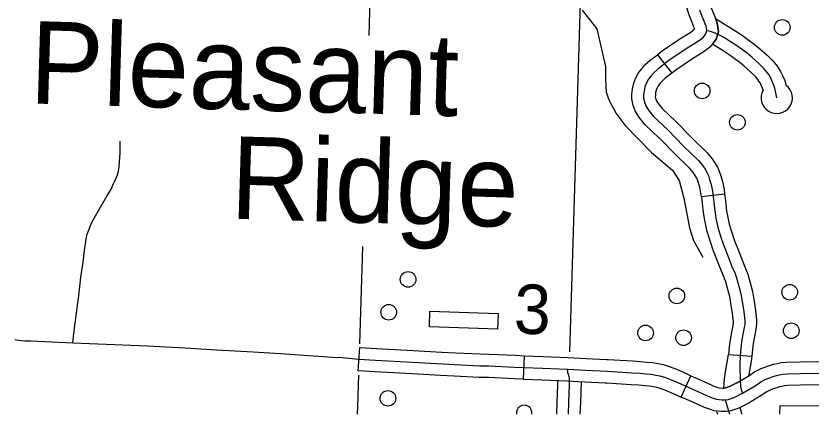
# Model space of a CAD drawing. Extents: x 653372 to 905732, y 627442 to 787275.
# Drawn here: x 695550 to 700643, y 728634 to 731183 of the extents above; entities that cross this region are included whole.
import ezdxf

# ---------------------------------------------------------------- set-up
doc = ezdxf.new("R2010")
doc.units = 0
for name, color, linetype in [('25', 7, 'Continuous'), ('31', 7, 'Continuous'), ('33', 7, 'Continuous'), ('35', 7, 'Continuous'), ('45', 7, 'Continuous'), ('5', 7, 'Continuous'), ('56', 7, 'Continuous'), ('6', 7, 'Continuous')]:
    doc.layers.add(name, color=color, linetype=linetype)

msp = doc.modelspace()

# ---------------------------------------------------------------- linework, layer by layer
at = {"layer": '31'}
for p, q in [((699658.2, 730935), (699750.2, 730816.5)), ((699773.6, 730509.8), (699773.6, 730509.8)), ((700089, 730042.6), (699940.2, 730024.1)), ((697741.2, 728911), (697751.9, 729060.6)), ((698804.4, 729007.3), (698797.9, 728857.4)), ((700113.6, 729014.9), (700263.3, 729004.1)), ((698270, 728881.2), (698270, 728881.2)), ((699810.7, 728742.9), (699872.9, 728879.4)), ((699872.9, 728879.4), (699872.9, 728879.4))]:
    msp.add_line(p, q, dxfattribs=at)
for points in [[(699844.1, 731243.5), (699846.2, 731233.1), (699856.9, 731197.1), (699874.1, 731153.1), (699889.1, 731116.2), (699895, 731098.1), (699895.1, 731097.8), (699890.1, 731092.1), (699872, 731077.9), (699801.9, 731034.8), (699688.2, 730958.4), (699658.2, 730935)], [(699991, 731273.9), (699991.9, 731269.6), (699998.9, 731245.7), (700013.4, 731208.8), (700030.1, 731167.8), (700040.2, 731136.7), (700045.8, 731109.7), (700049.8, 731081.3), (700034.5, 731035), (700015.7, 731007.8), (699993.6, 730982.6), (699957.8, 730954.6), (699883.1, 730908.6), (699776.2, 730836.7), (699750.2, 730816.5)], [(699927.9, 731221.4), (699943.7, 731181), (699959.6, 731142), (699967.6, 731117.4), (699971.9, 731096.8), (699973.1, 731088.2), (699966.6, 731068.8), (699956.5, 731054), (699941.8, 731037.4), (699914.9, 731016.2), (699842.5, 730971.7), (699732.2, 730897.5), (699660.9, 730842.2)], [(700010.9, 731002.3), (700034.5, 731035), (700049.8, 731081.3), (700040.2, 731136.7), (700030.2, 731167.5), (700160.8, 731085.1), (700209.3, 731053.3), (700247, 731026.8), (700279, 731003.2), (700313, 730975.2), (700360.8, 730931.8), (700395, 730897), (700418.5, 730870.8), (700433.7, 730849.5), (700447.3, 730827.4), (700460.2, 730801.9), (700473.6, 730769.8), (700482.6, 730738.4)], [(700422.7, 730658.3), (700416.9, 730691.2), (700409.4, 730721.4), (700402.7, 730744.9), (700392, 730770.6), (700381.8, 730790.8), (700371.2, 730808), (700359.8, 730823.8), (700340.3, 730845.7), (700308.8, 730877.7), (700263.8, 730918.5), (700232.9, 730944.1), (700203.2, 730965.9), (700167.2, 730991.3), (700120.2, 731022), (700088.8, 731041.9), (700056.2, 731059.4), (700027.3, 731073.1), (700003.9, 731081.9), (699989.9, 731085.3), (699973.1, 731088.2)], [(700335.5, 730707.2), (700331.8, 730720.1), (700323.8, 730739.2), (700316.3, 730754.1), (700308.7, 730766.4), (700301.2, 730776.9), (700285.6, 730794.3), (700256.8, 730823.6), (700214.7, 730861.8), (700186.8, 730884.9), (700159.4, 730905), (700125, 730929.2), (700079.6, 730958.9), (700010.9, 731002.3)], [(699670.5, 730400.9), (699578.4, 730488), (699539.7, 730536), (699515.5, 730574.8), (699502.7, 730609.8), (699494.5, 730651.8), (699495.4, 730682.3), (699498.3, 730715.5), (699507, 730752.8), (699521, 730786.8), (699537.6, 730818.9), (699558.1, 730845.1), (699578.6, 730869.3), (699612.9, 730899.9), (699658.2, 730935)], [(699660.9, 730842.2), (699632.4, 730816.8), (699616.2, 730797.8), (699601.1, 730778.3), (699589.2, 730755.2), (699578.7, 730729.8), (699572.5, 730703.6), (699570.3, 730677.9), (699569.7, 730657.9), (699575.2, 730630), (699583.3, 730607.9), (699600.9, 730579.6), (699633.6, 730539), (699724.5, 730453), (699826.1, 730350.2), (699920.6, 730256.7), (699948.3, 730222.8), (699963.3, 730201.4), (699976.7, 730178.6), (699985, 730161.3), (699993, 730136.7), (700002.2, 730104.3), (700011.2, 730061.1), (700019.8, 729991.6), (700023.9, 729949.1), (700027.5, 729922.7), (700032.8, 729888.4), (700046.1, 729830.1), (700063.4, 729773.6), (700082.1, 729717), (700102.4, 729663.8), (700135.5, 729579.5), (700153.2, 729538.6), (700165.4, 729506), (700180.4, 729453.5), (700193, 729403.8), (700203.3, 729341.7), (700211.5, 729289.3), (700216.1, 729250.7), (700218.4, 729229.7), (700218.5, 729214.6), (700217.2, 729204.4), (700214.8, 729188.9), (700208.4, 729155.5), (700197.4, 729096.8), (700191.8, 729055.6), (700188.4, 729009.4), (700185.5, 728944.2), (700187.5, 728847.2), (700190.8, 728812.6), (700195.5, 728790), (700203.1, 728767.9)], [(699750.2, 730816.5), (699708.9, 730784.5), (699686.2, 730764.3), (699674.4, 730750.4), (699664.5, 730737.7), (699657.3, 730723.7), (699650.3, 730706.7), (699646.8, 730691.8), (699645.2, 730673.5), (699644.9, 730664.1), (699647.6, 730650.2), (699651, 730640.9), (699662.2, 730623.1), (699688.8, 730590.1), (699773.6, 730509.8)], [(699773.6, 730509.8), (699777, 730506.6), (699879.1, 730403.2), (699976.2, 730307.3), (700008.2, 730268), (700026.4, 730242), (700043, 730213.8), (700054.8, 730189.2), (700064.7, 730158.6), (700075.1, 730122.2), (700085.2, 730073.4), (700089, 730042.6)], [(699940.2, 730024.1), (699937.1, 730048.9), (699929.4, 730086.4), (699921.3, 730114.8), (699915.2, 730133.4), (699910.4, 730143.3), (699900.1, 730160.8), (699888.5, 730177.5), (699865.1, 730206.2), (699773, 730297.1), (699672, 730399.4), (699670.5, 730400.9)], [(699940.2, 730024.1), (699945.2, 729983.4), (699949.4, 729940.5), (699953.2, 729911.9), (699959, 729874.3), (699973.6, 729810.7), (699991.9, 729750.8), (700011.5, 729691.8), (700032.5, 729636.7), (700066.1, 729550.9), (700083.6, 729510.5), (700086.9, 729501.7)], [(700089, 730042.6), (700094.3, 729999.8), (700098.4, 729957.7), (700101.7, 729933.5), (700106.5, 729902.6), (700118.6, 729849.4), (700134.9, 729796.3), (700152.8, 729742.2), (700172.4, 729690.8), (700204.8, 729608.1), (700222.8, 729566.6), (700227.4, 729554.3)], [(700227.4, 729554.3), (700236.7, 729529.5), (700252.8, 729473), (700266.5, 729419.2), (700277.3, 729353.6), (700285.8, 729299.6), (700290.6, 729259.3), (700293.4, 729233.8), (700293.5, 729210), (700291.5, 729194), (700288.7, 729176.1), (700282.1, 729141.5), (700271.5, 729084.8), (700266.4, 729047.8), (700263.3, 729004.1)], [(700086.9, 729501.7), (700094.1, 729482.6), (700107.9, 729434), (700119.5, 729388.4), (700129.2, 729329.8), (700137.2, 729279), (700141.6, 729242.1), (700143.4, 729225.5), (700143.5, 729219.2), (700142.9, 729214.8), (700140.9, 729201.7), (700134.7, 729169.4), (700123.3, 729108.8), (700117.1, 729063.3), (700113.6, 729014.9)], [(697751.9, 729060.6), (697858.2, 729053), (698094.6, 729040.1), (698277.4, 729031)], [(698277.4, 729031), (698365.3, 729026.6), (698523.5, 729018.5), (698581.8, 729016.7), (698747.2, 729009.8), (698804.4, 729007.3)], [(698804.4, 729007.3), (698925.5, 729002), (699086.5, 728996.6), (699201.2, 728990.3), (699332.6, 728983.2)], [(700241, 728877), (700166.8, 728833.5), (700120.9, 728809.7), (700093.5, 728800.9), (700083.1, 728799.7), (700087.3, 728859), (700093.5, 728904.4), (700104.9, 728965.1), (700113.6, 729014.9)], [(700263.3, 729004.1), (700258.9, 728971.8), (700252.3, 728937.2), (700241, 728877)], [(697746.6, 728985.8), (697853.5, 728978.2), (698090.6, 728965.2), (698361.5, 728951.7), (698520.5, 728943.5), (698579.1, 728941.8), (698744, 728934.9), (698922.6, 728927.1), (699083.1, 728921.6), (699197.1, 728915.4), (699339.5, 728907.7), (699494.3, 728898.7), (699544.8, 728895.2), (699584.7, 728892.1), (699618.1, 728888.6), (699649.2, 728883.8), (699674.8, 728877.7), (699710.5, 728866.9), (699742.7, 728855.2), (699789.8, 728834.8), (699897.3, 728785.8)], [(699332.6, 728983.2), (699343.7, 728982.6), (699499, 728973.5), (699550.3, 728970), (699591.4, 728966.8), (699627.8, 728963.1), (699663.7, 728957.5), (699694.4, 728950.1), (699734.1, 728938.1), (699770.5, 728924.9), (699820.3, 728903.3), (699872.9, 728879.4)], [(700289.7, 728908.8), (700321.9, 728924.7), (700346.3, 728934.9), (700376.8, 728945.2), (700402.6, 728953.1), (700425, 728957.8), (700450.8, 728963.1), (700484.5, 728966), (700572.4, 728967.7), (700726.6, 728970.7), (700801.3, 728971.9), (700835.6, 728973.3), (700834.5, 728973.2)], [(698270, 728881.2), (698086.7, 728890.3), (697848.7, 728903.3), (697741.2, 728911)], [(699872.9, 728879.4), (699928, 728854.2), (699998.8, 728822.9), (700016.1, 728815), (700039.2, 728806.6), (700053.1, 728802.3), (700074.6, 728799.7), (700086.1, 728799.7), (700093.5, 728800.9), (700120.9, 728809.7), (700166.8, 728833.5), (700243.3, 728878.6), (700282.8, 728905.5), (700289.7, 728908.8)], [(699897.3, 728785.8), (699968, 728754.5), (699987.6, 728745.5), (700015.3, 728735.5), (700037.3, 728728.7), (700070.1, 728724.7), (700092, 728724.8), (700110.8, 728727.6), (700149.9, 728740.3), (700203.1, 728767.9), (700283.5, 728815.2), (700320.7, 728840.5), (700352.9, 728856.4), (700372.7, 728864.6), (700399.8, 728873.8), (700421.4, 728880.4), (700440.3, 728884.4), (700461.5, 728888.8), (700488.4, 728891), (700573.9, 728892.7), (700727.9, 728895.7)], [(698797.9, 728857.4), (698740.8, 728859.9), (698576.4, 728866.8), (698517.4, 728868.6), (698357.7, 728876.8), (698270, 728881.2)], [(698797.9, 728857.4), (698919.7, 728852.1), (699079.8, 728846.7), (699193, 728840.5), (699324.5, 728833.4)], [(699324.5, 728833.4), (699335.3, 728832.8), (699489.5, 728823.8), (699539.3, 728820.4), (699577.9, 728817.4), (699608.5, 728814.2), (699634.6, 728810.2), (699655.2, 728805.3), (699686.8, 728795.7), (699715, 728785.5), (699759.4, 728766.3), (699810.7, 728742.9)], [(700849.8, 728823.9), (700846.4, 728823.6), (700805.6, 728821.9), (700729.3, 728820.7), (700575.3, 728817.7), (700492.3, 728816.1), (700472.2, 728814.4), (700455.7, 728811), (700440.3, 728807.7), (700422.8, 728802.4), (700399.1, 728794.4), (700383.9, 728788.1), (700355.9, 728774.3)], [(700355.9, 728774.3), (700358.5, 728775.6), (700323.7, 728751.8), (700239.4, 728702.2), (700178.9, 728670.8), (700128.1, 728654.4), (700097.9, 728649.8), (700065.7, 728649.6), (700021.5, 728655.1), (699991.5, 728664.4), (699959.2, 728676.1), (699937.2, 728686.2), (699866.6, 728717.4), (699810.7, 728742.9)], [(700092, 728724.8), (700107.2, 728676.5), (700121.1, 728633.5)], [(700036.8, 728650.4), (700042.2, 728633.5)], [(700186.5, 728674.8), (700194.9, 728648.8), (700197.5, 728633.5)]]:
    msp.add_lwpolyline(points, dxfattribs=at)
msp.add_arc((700422.7, 730658.3), 100, 150.7117, 53.2132, dxfattribs=at)
at = {"layer": '33'}
for points in [[(695914.1, 729090.3), (695921.2, 729150.6), (695938.3, 729282.7), (695952, 729391.3), (695966.1, 729510.4), (695980.8, 729606.4), (695989, 729681.7), (695994.8, 729722.9), (696000.4, 729756.2), (696007.2, 729784.9), (696018, 729817.4), (696030.1, 729848.6), (696046.8, 729879.6), (696059.2, 729902.2), (696133.2, 730028), (696157.5, 730069.9), (696171.4, 730098.4), (696188.3, 730135.4), (696200.4, 730165.9), (696207, 730188.7), (696211.8, 730217.4), (696214, 730248.2), (696217, 730303.3), (696218.2, 730380.7)], [(695542.6, 729112.1), (695566.8, 729107.6), (695585.8, 729104.7), (695610.2, 729103.2), (695645.3, 729102.1), (695734.5, 729097.9), (695914.1, 729090.3), (696128.4, 729080.8), (696390.1, 729069.9), (696633.3, 729057.2), (696834.2, 729045.9), (697069.6, 729031.3), (697243.7, 729021), (697578.4, 728999.1), (697638.6, 728995), (697746.6, 728985.8)]]:
    msp.add_lwpolyline(points, dxfattribs=at)
at = {"layer": '35'}
for points in [[(699177.1, 731219), (699270.4, 731099.8), (699325.5, 730859.3)], [(699325.5, 730859.3), (699326.9, 730777.9), (699329.2, 730693.9), (699349.9, 730641.6), (699393.4, 730557.6), (699450.9, 730480.9), (699620.1, 730309.4), (699756, 730196.3), (699797.3, 730128.3), (699828.6, 730015.2), (699863.3, 729825.9), (699890.5, 729745.1), (699948.4, 729639)]]:
    msp.add_lwpolyline(points, dxfattribs=at)
at = {"layer": '45'}
for points in [[(699089.3, 728633.5), (699092, 728710.4), (699095.6, 728819.2), (699094.6, 728858.9), (699092.5, 728874.2), (699088, 728886.6), (699085.4, 728898.2), (699084.1, 728905.7), (699083.1, 728921.6)], [(699014.3, 728633.5), (699014.3, 728634), (699017.1, 728712.9), (699020.6, 728819.5), (699019.9, 728848.7)], [(699164.4, 728633.5), (699167, 728707.8), (699171.4, 728841.7)]]:
    msp.add_lwpolyline(points, dxfattribs=at)
at = {"layer": '5'}
msp.add_lwpolyline([(699171.8, 731549.1), (699095.9, 729032.8)], dxfattribs=at)
at = {"layer": '56'}
msp.add_lwpolyline([(698197.7, 729192.8), (698201.3, 729292.8), (698638.5, 729277), (698634.9, 729177.1)], close=True, dxfattribs=at)
msp.add_lwpolyline([(700443.1, 728633.5), (700443.5, 728688.4), (700880.9, 728685.8), (700880.6, 728633.5)], dxfattribs=at)
for centre in [(700457.9, 731109.4), (699945.1, 730703), (700170.8, 730501.7), (698061.3, 729495.6), (700505.8, 729414), (699782.9, 729390.4), (697937.5, 729286), (699582.8, 729153.1), (700515.5, 729167.2), (699826.1, 729122.4), (697932.7, 728734.4)]:
    msp.add_circle(centre, 50, dxfattribs=at)
msp.add_arc((698805.2, 728640.1), 50, 352.4121, 187.5879, dxfattribs=at)
at = {"layer": '6'}
for points in [[(698829.4, 731564.5), (698158.8, 731603.1), (698063.1, 731537.2), (697820.9, 731444), (697809.3, 731057.8)], [(697768.6, 729707.3), (697766.4, 729633.8), (697749.5, 729082.9)], [(697743.4, 728882.3), (697737.2, 728682), (697735.7, 728633.5)]]:
    msp.add_lwpolyline(points, dxfattribs=at)

# ---------------------------------------------------------------- texts
at = {"layer": '25'}
for s, p in [('Pleasant', (695632.2, 730623.2)), ('Ridge', (696918.3, 729885.3))]:
    msp.add_text(s, height=528, rotation=358.28, dxfattribs=at).set_placement(p)
at = {"layer": '56'}
msp.add_text('3', height=316.8, rotation=358.28, dxfattribs=at).set_placement((698736.1, 729149.9))

doc.saveas('drawing.dxf')
